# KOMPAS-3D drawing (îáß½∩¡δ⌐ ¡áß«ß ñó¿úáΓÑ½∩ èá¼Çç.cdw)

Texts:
  Масляный насос двигателя КамАЗ
  Sanek
  Текст на чертеже
  Размерные надписи
  Шероховатость
  Линия-выноска #1
  Линия-выноска #2
  Линия-выноска #3
  Отклонения формы и база
  Заголовок таблицы
  Ячейка таблицы
  Стрелка вида
  Обозначение изменения
  Фигурная скобка
  Номер узла
  Марка координационной оси
  VRCB
  Выносная надпись
  Обозначение узла
  Марка/позиционное обозначение с линией-выноской
  Марка/позиционное обозначение на линии
  Марка/позиционное обозначение без линии-выноски
  Погрешность некоторых размеров  1 мм.
  Размеры снимал с насоса штангенциркулем
  Масляный насос
  двигателя КамАЗ
  Ефимов А.С.
  СГТУ ААХ
Dimensions and other numbers on the sheet: 7; 150; 137; 175; 1:1; 1; 0; 2; 3; 4; 5; 6; 8; 9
